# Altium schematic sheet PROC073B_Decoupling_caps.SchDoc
size 431 x 279 mm; Date: Not shown in title block; ApprovedBy: Not shown in title block; CheckedBy: Not shown in title block; Author: Not shown in title block; CompanyName: Not shown in title block; Engineer: Not shown in title block; Organization: Not shown in title block; Address1: Not shown in title block; Address2: Not shown in title block; Address3: Not shown in title block; Address4: Not shown in title block; DocumentNumber: 1; Revision: Use project parameter SCH_Rev; SheetNumber: 5; SheetTotal: 9; PageSetup: Record=PageOptions¦CenterHorizontal=True¦CenterVertical=True¦PrintScale=1.00¦XCorrection=1.00¦YCorrection=1.00¦PrintKind=0¦BorderSize=5000000¦LeftOffset=0¦BottomOffset=0¦Orientation=2¦PaperLength=1000¦PaperWidth=1000¦Scale=100¦PaperSource=15¦PrintQuality=600¦MediaType=1¦DitherType=10¦PaperKind=Letter¦PrintScaleMode=1
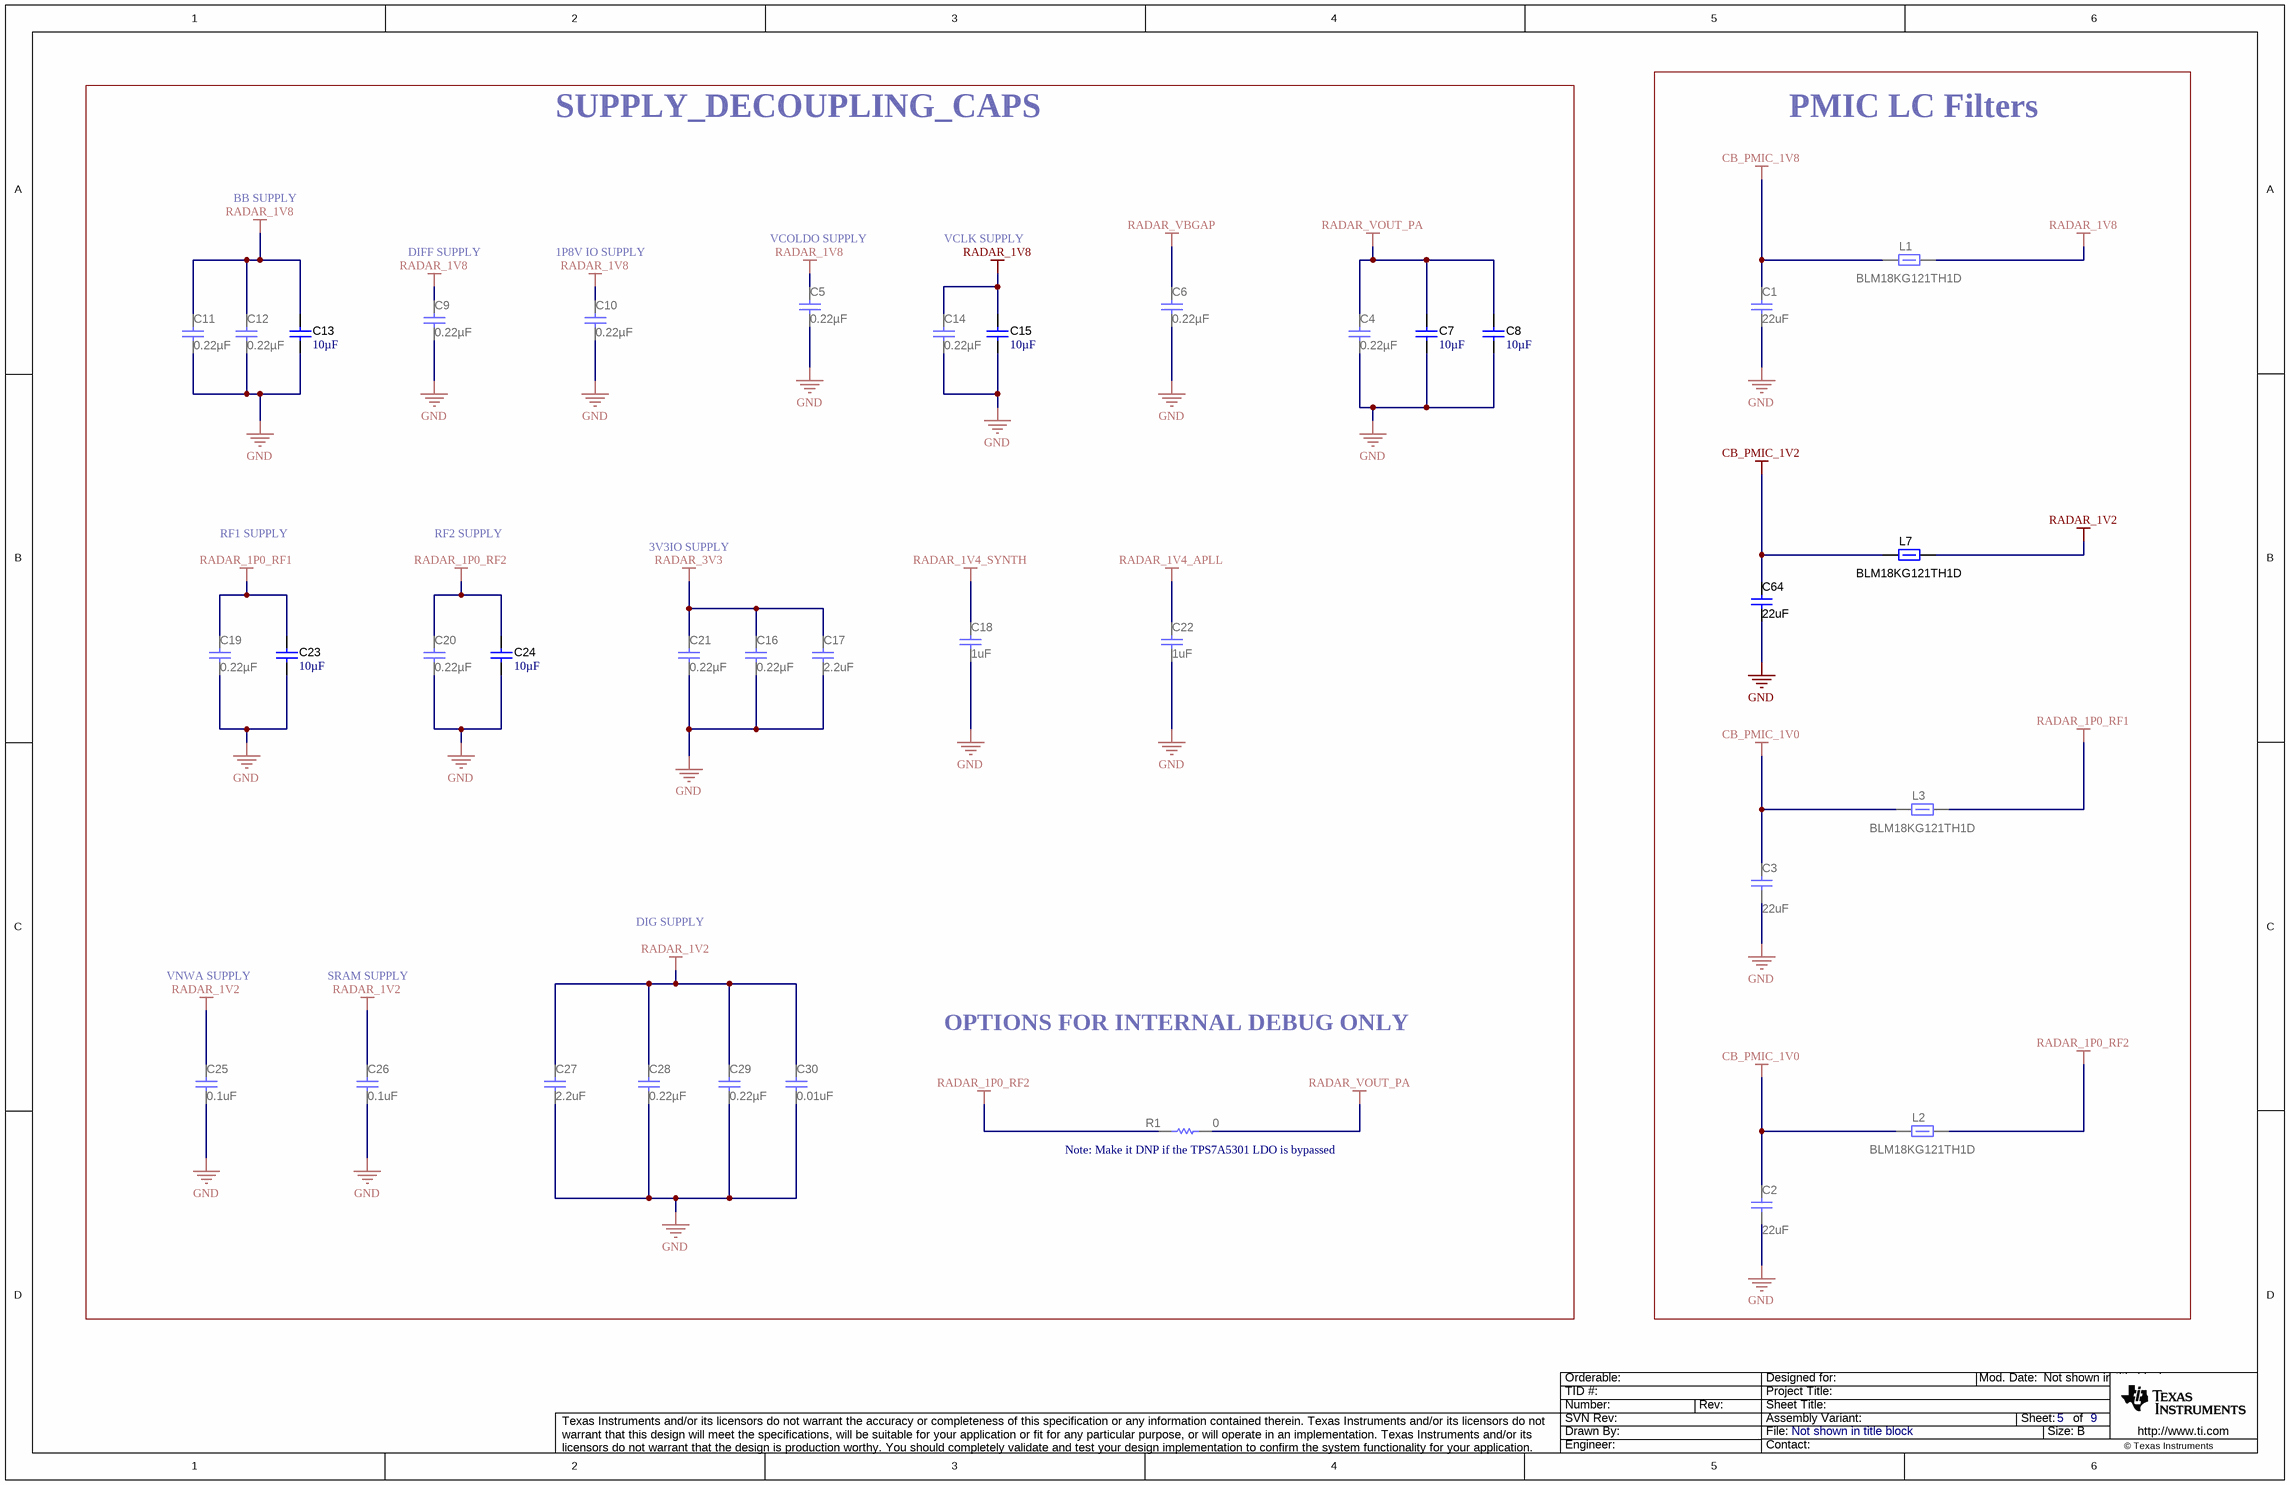
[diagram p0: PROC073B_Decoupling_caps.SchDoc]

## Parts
C1  ValueDisplayed: 22uF  [1206_180]  (hidden comment: CGA5L1X7R0J226M160AC)
C2  ValueDisplayed: 22uF  [1206_180]  (hidden comment: CGA5L1X7R0J226M160AC)
C3  ValueDisplayed: 22uF  [1206_180]  (hidden comment: CGA5L1X7R0J226M160AC)
C4  ValueDisplayed: 0.22µF  [0402L]  (hidden comment: GCM155R71C224KE02D)
C5  ValueDisplayed: 0.22µF  [0402L]  (hidden comment: GCM155R71C224KE02D)
C6  ValueDisplayed: 0.22µF  [0402L]  (hidden comment: GCM155R71C224KE02D)
C7  ValueDisplayed: 10µF  [0805_HV]  (hidden comment: GRM21BR71A106KA73L)
C8  ValueDisplayed: 10µF  [0805_HV]  (hidden comment: GRM21BR71A106KA73L)
C9  ValueDisplayed: 0.22µF  [0402L]  (hidden comment: GCM155R71C224KE02D)
C10  ValueDisplayed: 0.22µF  [0402L]  (hidden comment: GCM155R71C224KE02D)
C11  ValueDisplayed: 0.22µF  [0402L]  (hidden comment: GCM155R71C224KE02D)
C12  ValueDisplayed: 0.22µF  [0402L]  (hidden comment: GCM155R71C224KE02D)
C13  ValueDisplayed: 10µF  [0805_HV]  (hidden comment: GRM21BR71A106KA73L)
C14  ValueDisplayed: 0.22µF  [0402L]  (hidden comment: GCM155R71C224KE02D)
C15  ValueDisplayed: 10µF  [0805_HV]  (hidden comment: GRM21BR71A106KA73L)
C16  ValueDisplayed: 0.22µF  [0402L]  (hidden comment: GCM155R71C224KE02D)
C17  ValueDisplayed: 2.2uF  [0603]  (hidden comment: GCM188R70J225KE22D)
C18  ValueDisplayed: 1uF  [0603]  (hidden comment: GCM188R71C105KA64D)
C19  ValueDisplayed: 0.22µF  [0402L]  (hidden comment: GCM155R71C224KE02D)
C20  ValueDisplayed: 0.22µF  [0402L]  (hidden comment: GCM155R71C224KE02D)
C21  ValueDisplayed: 0.22µF  [0402L]  (hidden comment: GCM155R71C224KE02D)
C22  ValueDisplayed: 1uF  [0603]  (hidden comment: GCM188R71C105KA64D)
C23  ValueDisplayed: 10µF  [0805_HV]  (hidden comment: GRM21BR71A106KA73L)
C24  ValueDisplayed: 10µF  [0805_HV]  (hidden comment: GRM21BR71A106KA73L)
C25  ValueDisplayed: 0.1uF  [0402L]  (hidden comment: GCM155R71C104KA55D)
C26  ValueDisplayed: 0.1uF  [0402L]  (hidden comment: GCM155R71C104KA55D)
C27  ValueDisplayed: 2.2uF  [0603]  (hidden comment: GCM188R70J225KE22D)
C28  ValueDisplayed: 0.22µF  [0402L]  (hidden comment: GCM155R71C224KE02D)
C29  ValueDisplayed: 0.22µF  [0402L]  (hidden comment: GCM155R71C224KE02D)
C30  ValueDisplayed: 0.01uF  [0402L]  (hidden comment: GCM155R71E103KA37D)
C64  ValueDisplayed: 22uF  [1206_180]  (hidden comment: CGA5L1X7R0J226M160AC)
L1  BLM18KG121TH1D  [0603]
L2  BLM18KG121TH1D  [0603]
L3  BLM18KG121TH1D  [0603]
L7  BLM18KG121TH1D  [0603]
R1  ValueDisplayed: 0  [0603]  (hidden comment: MCT06030Z0000ZP500)

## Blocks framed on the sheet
SUPPLY_DECOUPLING_CAPS: C4-C30 R1
PMIC LC Filters: C1-C3 C64 L1-L3 L7

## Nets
CB_PMIC_1V0: C2.2 C3.2 L2.1 L3.1
CB_PMIC_1V2: C64.2 L7.1
CB_PMIC_1V8: C1.2 L1.1
GND: C1.1 C2.1 C3.1 C4.1 C5.1 C6.1 C7.1 C8.1 C9.1 C10.1 C11.1 C12.1 C13.1 C14.1 C15.1 C16.1 C17.1 C18.1 C19.1 C20.1 C21.1 C22.1 C23.1 C24.1 C25.1 C26.1 C27.1 C28.1 C29.1 C30.2 C64.1
RADAR_1P0_RF1: C19.2 C23.2 L3.2
RADAR_1P0_RF2: C20.2 C24.2 L2.2 R1.1
RADAR_1V2: C25.2 C26.2 C27.2 C28.2 C29.2 C30.1 L7.2
RADAR_1V4_APLL: C22.2
RADAR_1V4_SYNTH: C18.2
RADAR_1V8: C5.2 C9.2 C10.2 C11.2 C12.2 C13.2 C14.2 C15.2 L1.2
RADAR_3V3: C16.2 C17.2 C21.2
RADAR_VBGAP: C6.2
RADAR_VOUT_PA: C4.2 C7.2 C8.2 R1.2

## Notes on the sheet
- BB SUPPLY
- DIFF SUPPLY
- 1P8V IO SUPPLY
- VCOLDO SUPPLY
- VCLK SUPPLY
- RF1 SUPPLY
- RF2 SUPPLY
- 3V3IO SUPPLY
- DIG SUPPLY
- VNWA SUPPLY
- SRAM SUPPLY
- OPTIONS FOR INTERNAL DEBUG ONLY
- (near R1) Note: Make it DNP if the TPS7A5301 LDO is bypassed

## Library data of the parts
C1-C3 C64 = CMP-0008770-2: CAP, CERM, 22 uF, 6.3 V, +/- 10%, X7R, AEC-Q200 Grade 1, 1206; Manufacturer: TDK; TaMin_C: -55°C; ESR_ohm: 1.872m; Polarized: N; SizeAreaWB_mm2: 10.92; Value1: 0.001872 ohm; U/M: EA; Value: 22uF; SizeZ_mm: 1.8; SizeX_mm: 3.2; SizeY_mm: 1.6; Value2: 6.3V; SizeArea_mm2: 5.12; CompType: Capacitor; AEC Qualified: Y; Cap_F: 22µF; IRMS_A: 5.30203A; AEC Grade: 1; AEC Category: Q200; TaMax_C: 125°C; INSTALLATION: DNP
C4-C6 C9-C12 C14 C16 C19-C21 C28 C29 = CMP-0078265-1: CAP, CERM, 0.22 µF, 16 V,+/- 10%, X7R, AEC-Q200 Grade 1, 0402; Manufacturer: MuRata; TaMin_C: -55°C; Polarized: N; SizeAreaWB_mm2: 3; U/M: EA; Value: 0.22uF; TaMax_C: 125°C; SizeZ_mm: 0.6; SizeX_mm: 1; SizeY_mm: 0.5; Cap_Case: 0402; Value2: 16V; CompType: Capacitor; AEC Qualified: Y; Cap_F: 220nF; AEC Category: Q200
C7 C8 C13 C15 C23 C24 = CMP-0081849-1: CAP, CERM, 10 µF,  V,+/- 10%, X7R, 0805; Manufacturer: MuRata; TaMin_C: -55°C; Polarized: N; Green_Lifecycle: Active; SizeAreaWB_mm2: 6.75; Green_REACh: Passed; U/M: EA; Value: 10uF; TaMax_C: 125°C; SizeZ_mm: 1.45; SizeX_mm: 2; SizeY_mm: 1.25; Cap_Case: 0805; SizeArea_mm2: 2.5; AEC Category: Q200
C17 C27 = CMP-0007134-5: CAP, CERM, 2.2 uF, 6.3 V, +/- 10%, X7R, AEC-Q200 Grade 1, 0603; Manufacturer: MuRata; TaMin_C: -55°C; Polarized: N; SizeAreaWB_mm2: 4.68; Value1: Unknown; U/M: EA; Value: 2.2uF; TaMax_C: 125°C; SizeZ_mm: 1; SizeX_mm: 1.6; SizeY_mm: 0.8; Value2: 6.3V; SizeArea_mm2: 1.28; CompType: Capacitor; AEC Qualified: Y; Cap_F: 2.2µF; AEC Category: Q200
C18 C22 = CMP-0007136-5: CAP, CERM, 1 uF, 16 V, +/- 10%, X7R, AEC-Q200 Grade 1, 0603; Manufacturer: MuRata; TaMin_C: -55°C; Polarized: N; SizeAreaWB_mm2: 4.68; Value1: Unknown; U/M: EA; Value: 1uF; TaMax_C: 125°C; SizeZ_mm: 1; SizeX_mm: 1.6; SizeY_mm: 0.8; Value2: 16V; SizeArea_mm2: 1.28; CompType: Capacitor; AEC Qualified: Y; Cap_F: 1µF; AEC Category: Q200
C25 C26 = CMP-0006351-2: CAP, CERM, 0.1 uF, 16 V, +/- 10%, X7R, 0402; Manufacturer: MuRata; TaMin_C: -55°C; Polarized: N; SizeAreaWB_mm2: 3; Value1: Unknown; U/M: EA; Value: 0.1uF; TaMax_C: 125°C; SizeZ_mm: 0.6; SizeX_mm: 1; SizeY_mm: 0.5; Cap_Case: 0402; Value2: 16V; CompType: Capacitor; Cap_F: 100nF; AEC Category: Q200
C30 = CMP-0006352-2: CAP, CERM, 0.01 uF, 25 V, +/- 10%, X7R, 0402; Manufacturer: MuRata; TaMin_C: -55°C; Polarized: N; SizeAreaWB_mm2: 3; Value1: Unknown; U/M: EA; Value: 0.01uF; TaMax_C: 125°C; SizeZ_mm: 0.6; SizeX_mm: 1; SizeY_mm: 0.5; Cap_Case: 0402; Value2: 25V; CompType: Capacitor; Cap_F: 10nF; AEC Category: Q200
L1-L3 L7 = CMP-0077879-2: Ferrite Bead, 120 ohm @ 100 MHz, 1.9 A, 0603; Manufacturer: MuRata; ZTyp@100MHz_Ohm: 120; SizeAreaWB_mm2: 4.68; DCR_ohm: 0.04; Value1: 0.04 ohm; Value: 120 ohm; Imax_A: 1.9A; SizeZ_mm: 1.0; SizeX_mm: 1.6; SizeY_mm: 0.8; SizeArea_mm2: 1.28
R1 = CMP-0025884-3: RES, 0, 5%, 0.125 W, 0603; Manufacturer: Vishay/Beyschlag; Power_W: 125mW; TempCo: ppm/C; Value_Code: 0000; U/M: EA; Value: 0; EIA_Code: E24; SizeX_mm: 1.6; SizeY_mm: 0.8; SizeZ_mm: 1; Value2: 0.125W; SizeArea_mm2: 1.28; CompType: Resistor; AEC Qualified: N; AEC Category: Q200; INSTALATION: DNP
